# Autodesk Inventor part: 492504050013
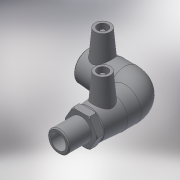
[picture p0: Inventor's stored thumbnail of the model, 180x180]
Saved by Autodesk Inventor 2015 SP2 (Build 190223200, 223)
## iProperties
Created: 2017-06
Part Number: 492504050013
Material: Generic
Description: PLASSON 90° ELBOW MALE TRANSITION 50-1.1/4"
Document SubType Name: Modeling
Designer: KIM
Mass: 294.062 g
Surface Area: 667.71 cm^2
Volume: 294.062 cm^3
Density: 1 g/cm^3
Appearance: Default
Author: KIM
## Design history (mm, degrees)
derived "492504.ipt"
feature "Solid1::492504.ipt"
tag "TaggingFeature1"
body "Solid1"
other parameters: "d2" = 67, "d4" = 36, "d5" = 60.3, "d8" = 168 deg, "d10" = 19.2, "d11" = 6.4, "d29" = 52, "d30" = 15, "d31" = 59.4, "d34" = 5 deg, "d41" = 4, "d42" = 14, "d43" = 0, "d48" = 74.5, "d50" = 42.5, "d51" = 19.2, "d52" = 48, "d54" = 90 deg, "d58" = 48, "d59" = 0, "d61" = 90 deg, "d86" = 3, "d87" = 0, "d93" = 0.1, "d94" = 9, "d95" = 41.91, "d96" = 29.337, "d97" = 38, "d98" = 36, "d99" = 67, "d100" = 32.4, "d102" = 2.5, "d106" = 0, "L_" = 144, "L_1" = 48, "D_" = 38, "A_" = 52, "d_2" = 12, "L_2" = 36, "D_1" = 67, "R_" = 41.91
